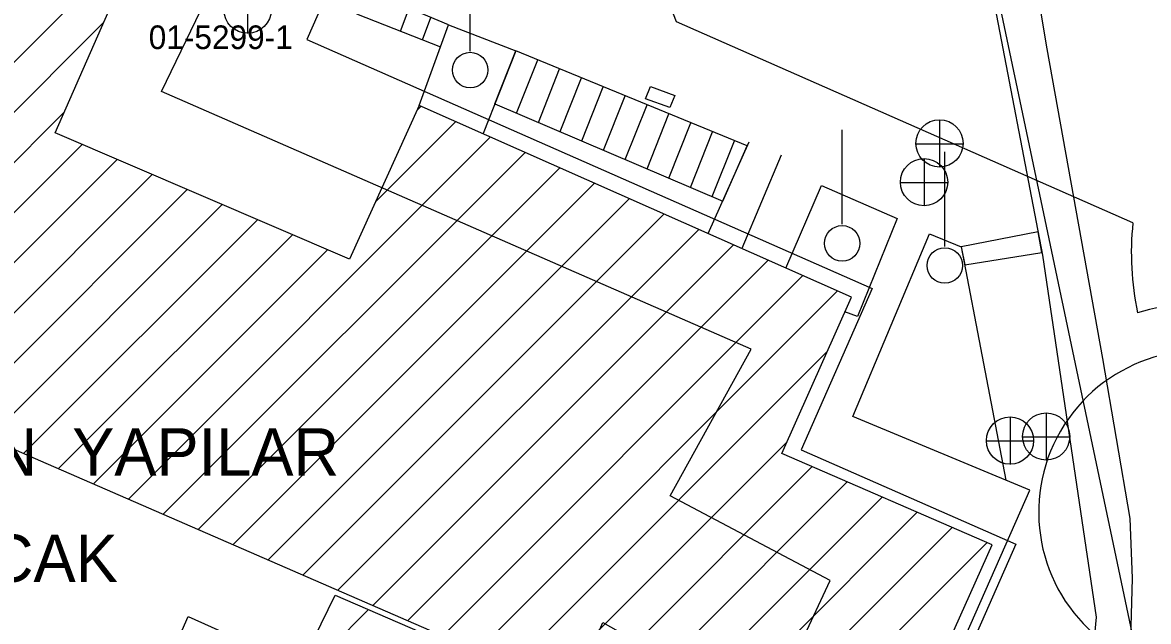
# Model space of a CAD drawing. Extents: x 419101 to 420177, y 4451541 to 4452254.
# Drawn here: x 419816.37 to 419864.02, y 4451704.08 to 4451729.44 of the extents above; entities that cross this region are included whole.
import ezdxf

# ---------------------------------------------------------------- set-up
doc = ezdxf.new("R2010")
doc.units = 0
for name, color, linetype in [('2_KADASTRO', 7, 'Continuous'), ('3_HALİHAZIR', 7, 'Continuous'), ('Level 10', 7, 'Continuous'), ('Level 28', 7, 'Continuous'), ('Level 29', 7, 'Continuous'), ('Level 62', 7, 'Continuous')]:
    doc.layers.add(name, color=color, linetype=linetype)

msp = doc.modelspace()

# ---------------------------------------------------------------- linework, layer by layer
at = {"layer": '2_KADASTRO'}
msp.add_lwpolyline([(419789.195, 4451663.821), (419792.466, 4451722.195), (419796.208, 4451788.966), (419796.952, 4451802.25), (419802.028, 4451804.087), (419846.019, 4451820.004), (419846.711, 4451808.426), (419850.52, 4451780.325), (419850.846, 4451775.043), (419851.91, 4451757.789), (419863.818, 4451701.263), (419862.735, 4451692.788), (419853.795, 4451660.742)], close=True, dxfattribs=at)
at = {"layer": '3_HALİHAZIR'}
for p, q in [((419804.613, 4451716.365), (419821.461, 4451733.212)), ((419835.312, 4451728.229), (419835.312, 4451732.229)), ((419825.91, 4451728.97), (419825.91, 4451730.97)), ((419832.367, 4451729.074), (419832.727, 4451730.039)), ((419833.297, 4451728.708), (419833.65, 4451729.652)), ((419806.088, 4451715.719), (419819.801, 4451729.431)), ((419836.362, 4451725.996), (419837.25, 4451728.236)), ((419837.282, 4451725.603), (419838.175, 4451727.856)), ((419838.202, 4451725.21), (419839.1, 4451727.476)), ((419839.122, 4451724.817), (419840.025, 4451727.096)), ((419840.042, 4451724.424), (419840.95, 4451726.716)), ((419840.962, 4451724.031), (419841.875, 4451726.335)), ((419833.069, 4451725.729), (419833.235, 4451725.895)), ((419841.882, 4451723.638), (419842.8, 4451725.955)), ((419807.564, 4451715.073), (419818.141, 4451725.65)), ((419831.316, 4451721.855), (419834.705, 4451725.243)), ((419842.802, 4451723.245), (419843.725, 4451725.575)), ((419855.194, 4451723.311), (419855.194, 4451725.311)), ((419843.722, 4451722.852), (419844.65, 4451725.195)), ((419844.642, 4451722.459), (419845.575, 4451724.815)), ((419851.058, 4451720.894), (419851.058, 4451724.894)), ((419820.849, 4451709.266), (419836.174, 4451724.592)), ((419845.561, 4451722.066), (419846.5, 4451724.434)), ((419854.174, 4451724.301), (419856.174, 4451724.301)), ((419809.039, 4451714.427), (419818.888, 4451724.276)), ((419822.327, 4451708.623), (419837.644, 4451723.94)), ((419855.4, 4451719.957), (419855.4, 4451723.958)), ((419810.514, 4451713.781), (419820.372, 4451723.639)), ((419854.541, 4451721.671), (419854.541, 4451723.671)), ((419811.99, 4451713.135), (419821.856, 4451723.001)), ((419823.805, 4451707.98), (419839.113, 4451723.288)), ((419825.283, 4451707.337), (419840.583, 4451722.636)), ((419853.521, 4451722.661), (419855.521, 4451722.661)), ((419813.465, 4451712.489), (419823.34, 4451722.364)), ((419826.762, 4451706.693), (419842.052, 4451721.984)), ((419814.94, 4451711.843), (419824.824, 4451721.727)), ((419816.415, 4451711.197), (419826.308, 4451721.089)), ((419828.24, 4451706.05), (419843.522, 4451721.332)), ((419829.718, 4451705.407), (419844.991, 4451720.681)), ((419817.892, 4451710.552), (419827.792, 4451720.452)), ((419831.196, 4451704.764), (419846.461, 4451720.029)), ((419819.37, 4451709.909), (419829.276, 4451719.815)), ((419832.674, 4451704.121), (419847.93, 4451719.377)), ((419834.153, 4451703.478), (419849.4, 4451718.725)), ((419835.631, 4451702.835), (419850.869, 4451718.073)), ((419837.109, 4451702.192), (419850.423, 4451715.506)), ((419859.709, 4451710.905), (419859.709, 4451712.905)), ((419858.18, 4451710.733), (419858.18, 4451712.733)), ((419838.587, 4451701.548), (419848.725, 4451711.686)), ((419857.16, 4451711.723), (419859.16, 4451711.723)), ((419858.689, 4451711.895), (419860.689, 4451711.895)), ((419840.065, 4451700.905), (419849.797, 4451710.637)), ((419841.544, 4451700.262), (419851.276, 4451709.994)), ((419843.022, 4451699.619), (419852.755, 4451709.352)), ((419844.5, 4451698.976), (419854.234, 4451708.71)), ((419845.978, 4451698.333), (419855.713, 4451708.067)), ((419847.456, 4451697.69), (419857.191, 4451707.425)), ((419817.628, 4451691.194), (419831.019, 4451704.585))]:
    msp.add_line(p, q, dxfattribs=at)
for points in [[(419854.108, 4451764.505), (419857.462, 4451741.765), (419859.72, 4451728.319), (419862.073, 4451715.212), (419863.24, 4451708.443), (419863.339, 4451705.916), (419863.196, 4451700.825), (419862.751, 4451694.807), (419862.57, 4451691.986), (419862.417, 4451689.935), (419861.848, 4451686.413), (419861.411, 4451684.412), (419860.478, 4451681.371), (419859.193, 4451677.903), (419858.463, 4451675.539), (419857.204, 4451671.483), (419853.588, 4451659.531)], [(419811.378, 4451742.472), (419800.772, 4451718.047), (419817.131, 4451710.883), (419852.178, 4451695.635), (419857.403, 4451707.333), (419848.507, 4451711.197), (419851.45, 4451717.815), (419833.16, 4451725.929), (419830.212, 4451719.413), (419817.752, 4451724.764), (419823.321, 4451737.451)], [(419857.33, 4451731.138), (419859.539, 4451719.583), (419861.804, 4451704.269), (419860.819, 4451693.752)], [(419833.16, 4451725.929), (419834.402, 4451729.337)], [(419834.402, 4451729.337), (419837.249, 4451728.237), (419835.859, 4451724.731)], [(419845.39, 4451720.503), (419847.123, 4451724.392)], [(419848.482, 4451723.826), (419846.82, 4451719.869)], [(419848.68, 4451719.044), (419850.183, 4451722.533), (419853.385, 4451721.142), (419851.709, 4451716.993), (419851.171, 4451717.186)], [(419853.443, 4451698.469), (419853.982, 4451698.258), (419859.008, 4451709.645), (419851.508, 4451712.756), (419854.756, 4451720.485)], [(419854.756, 4451720.485), (419856.101, 4451719.947), (419857.983, 4451710.07)]]:
    msp.add_lwpolyline(points, dxfattribs=at)
for points in [[(419831.879, 4451733.49), (419830.502, 4451729.806), (419834.063, 4451728.407), (419834.402, 4451729.337), (419832.205, 4451730.259), (419833.299, 4451732.922)], [(419837.249, 4451728.237), (419836.361, 4451725.997), (419846.003, 4451721.878), (419847.042, 4451724.211)], [(419842.729, 4451726.206), (419842.948, 4451726.722), (419843.973, 4451726.344), (419843.764, 4451725.842)], [(419856.248, 4451719.175), (419859.516, 4451719.707), (419859.349, 4451720.578), (419856.101, 4451719.947)], [(419838.567, 4451701.324), (419837.334, 4451698.232), (419842.25, 4451696.138), (419834.022, 4451677.207), (419815.051, 4451685.33), (419823.383, 4451704.294), (419828.121, 4451702.171), (419829.599, 4451705.199)]]:
    msp.add_lwpolyline(points, close=True, dxfattribs=at)
for centre, radius in [((419825.895, 4451729.978), 1), ((419835.314, 4451727.424), 0.75), ((419855.179, 4451724.319), 1), ((419854.526, 4451722.679), 1), ((419851.06, 4451720.089), 0.75), ((419855.402, 4451719.152), 0.75), ((419859.694, 4451711.913), 1), ((419858.164, 4451711.741), 1)]:
    msp.add_circle(centre, radius, dxfattribs=at)
at = {"layer": 'Level 10'}
msp.add_lwpolyline([(420016.291, 4451685.44), (419931.368, 4451675.776), (419930.121, 4451689.721), (419926.913, 4451693.118), (419881.377, 4451699.349), (419876.03, 4451694.343), (419866.239, 4451664.345), (419831.309, 4451681.508), (419840.932, 4451704.034), (419847.883, 4451700.101), (419850.556, 4451705.822), (419843.784, 4451709.398), (419847.208, 4451715.607), (419822.258, 4451726.513), (419833.485, 4451749.755)], dxfattribs=at)
at = {"layer": 'Level 28'}
for points in [[(419838.371, 4451794.443), (419835.5, 4451787.961), (419843.796, 4451784.147), (419831.069, 4451755.265), (419838.639, 4451751.929), (419828.408, 4451728.71), (419852.325, 4451718.171)], [(419863.364, 4451720.956), (419844.041, 4451729.471), (419841.482, 4451736.064), (419850.56, 4451756.669), (419854.933, 4451756.687), (419862.123, 4451771.082), (419866.924, 4451769.168), (419869.4, 4451774.123), (419882.883, 4451767.482), (419882.958, 4451766.42), (419892.695, 4451767.501), (419890.171, 4451761.447), (419869.153, 4451759.186), (419864.895, 4451749.754)], [(419852.325, 4451718.171), (419849.321, 4451711.355), (419858.406, 4451707.352), (419852.325, 4451693.55), (419842.935, 4451697.688), (419833.393, 4451675.834)]]:
    msp.add_lwpolyline(points, dxfattribs=at)
for centre, radius, start, end in [((419875.596, 4451719.683), 12.298, 174.059, 191.9044), ((419866.22, 4451708.713), 8.843, 0.4791, 107.4889)]:
    msp.add_arc(centre, radius, start, end, dxfattribs=at)
at = {"layer": 'Level 62'}
msp.add_arc((419866.22, 4451708.713), 6.843, 346.9251, 231.495, dxfattribs=at)

# ---------------------------------------------------------------- texts
at = {"layer": '2_KADASTRO'}
msp.add_text('01-5299-1', height=1, dxfattribs=at).set_placement((419821.71, 4451728.312))
at = {"layer": 'Level 29'}
for s, p in [('VAR OLAN  YAPILAR', (419803.461, 4451710.261)), ('KORUNACAK', (419803.461, 4451705.761))]:
    msp.add_text(s, height=2, dxfattribs=at).set_placement(p)

doc.saveas('drawing.dxf')
